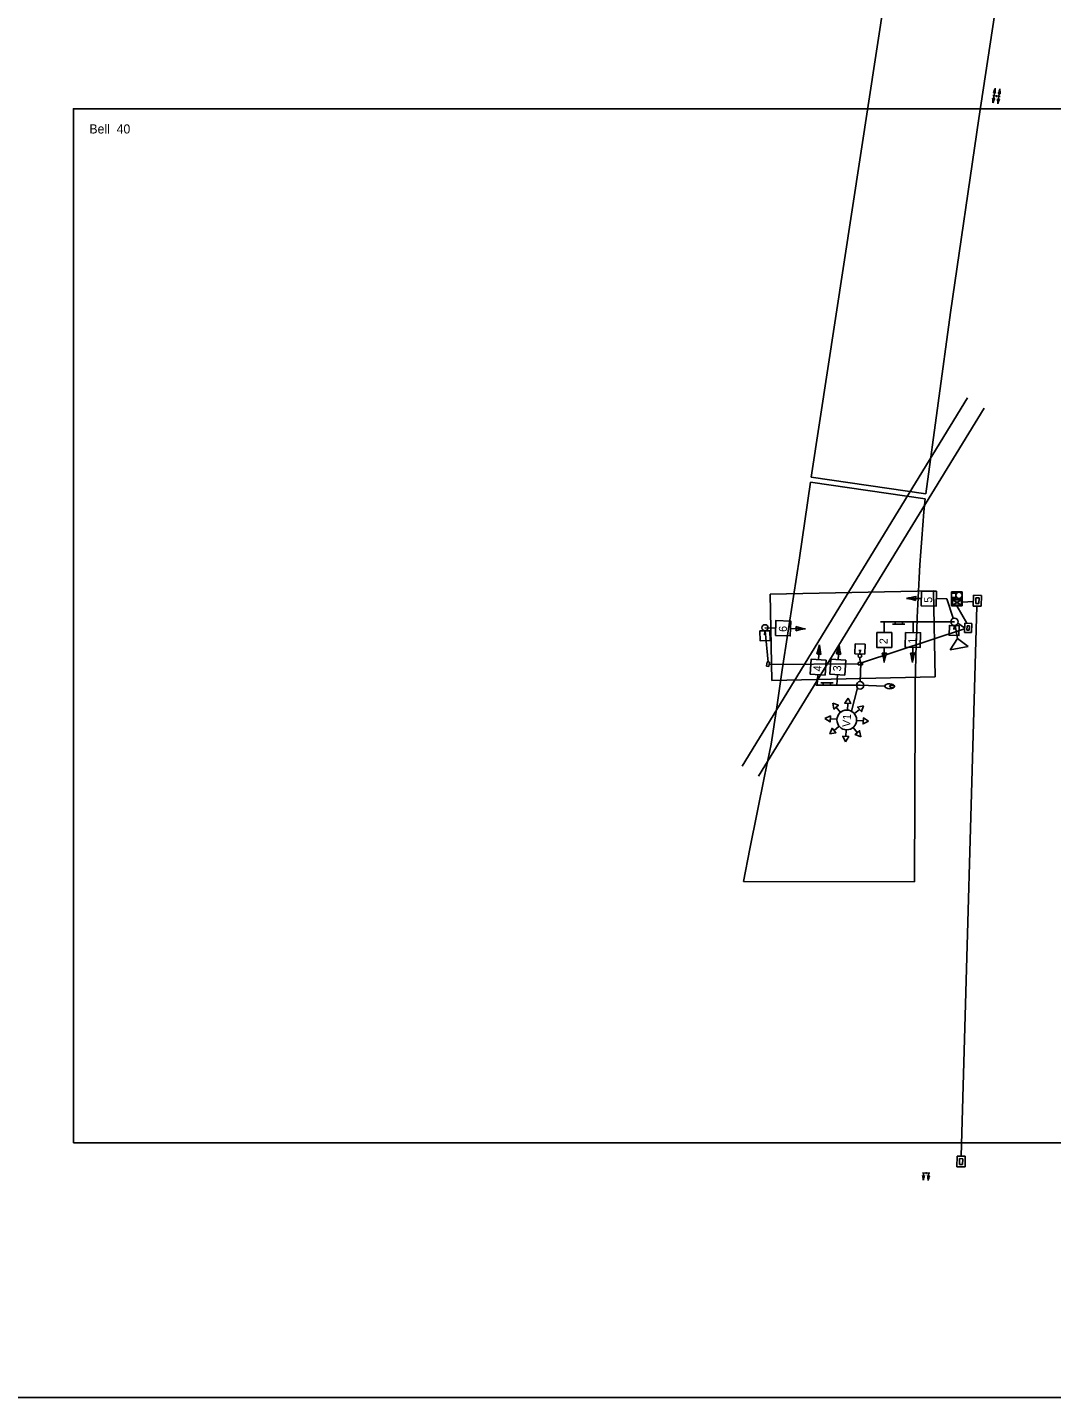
# Model space of a CAD drawing. Extents: x 991933 to 997296, y 1973751 to 1976728.
# Drawn here: x 992632 to 993048, y 1974815 to 1975371 of the extents above; entities that cross this region are included whole.
import ezdxf

# ---------------------------------------------------------------- set-up
doc = ezdxf.new("R2010")
doc.units = 0
for name, color, linetype in [('Level 23', 7, 'Continuous'), ('Level 5', 7, 'Continuous'), ('Level 51', 7, 'Continuous'), ('Level 53', 7, 'Continuous'), ('S_CROSS_DRAIN', 7, 'Continuous'), ('S_CURB', 7, 'Continuous'), ('S_DRIVEWAY', 7, 'Continuous'), ('S_DROP_INLET', 7, 'Continuous'), ('S_PARKING', 7, 'Continuous'), ('S_PAVEMENT_CROWN', 7, 'Continuous'), ('S_SHOULDER', 7, 'Continuous'), ('S_SIDEWALK', 7, 'Continuous')]:
    doc.layers.add(name, color=color, linetype=linetype)

msp = doc.modelspace()

# ---------------------------------------------------------------- linework, layer by layer
at = {"layer": 'Level 23'}
for points in [[(992469.7, 1974814.53), (993459.71, 1974814.53), (993459.71, 1975444.53), (992469.7, 1975444.53)], [(992651, 1974917.97), (993311, 1974917.97), (993311, 1975337.97), (992651, 1975337.97)]]:
    msp.add_lwpolyline(points, close=True, dxfattribs=at)
at = {"layer": 'Level 5'}
for p, q in [((992995.39, 1975481.31), (992950.59, 1975188.29)), ((992950.59, 1975188.29), (992997.14, 1975181.55))]:
    msp.add_line(p, q, dxfattribs=at)
msp.add_lwpolyline([(992997.14, 1975181.55), (993007.15, 1975255.28), (993018.62, 1975333.96), (993027.84, 1975394.67), (993039.93, 1975474.46)], dxfattribs=at)
at = {"layer": 'Level 51'}
for p, q in [((992933.93, 1975140.82), (993000.22, 1975142.21)), ((993000.22, 1975142.21), (993000.95, 1975107.22)), ((992934.66, 1975105.83), (992933.93, 1975140.82)), ((993000.95, 1975107.22), (992934.66, 1975105.83))]:
    msp.add_line(p, q, dxfattribs=at)
at = {"layer": 'Level 53'}
for p, q in [((992996.85, 1975179.57), (992950.31, 1975186.31)), ((992992.51, 1975023.97), (992992.77, 1975093.76)), ((992923.1, 1975024.2), (992992.51, 1975023.97))]:
    msp.add_line(p, q, dxfattribs=at)
msp.add_lwpolyline([(992950.31, 1975186.31), (992950.31, 1975186.31), (992950.31, 1975186.31), (992950.31, 1975186.31), (992950.31, 1975186.31), (992948.02, 1975170.5), (992945.89, 1975155.59), (992943.45, 1975139.92), (992941.13, 1975124.98), (992938.81, 1975110.04), (992936.59, 1975094.9), (992934.31, 1975079.89), (992931.67, 1975066.87), (992928.68, 1975052.14), (992925.71, 1975037.42), (992923.1, 1975024.2)], dxfattribs=at)
msp.add_arc((993972.15, 1975090.11), 979.39, 174.75942, 179.78648, dxfattribs=at)
at = {"layer": 'S_CROSS_DRAIN'}
for p, q in [((992988.64, 1975128.6), (992983.64, 1975128.6)), ((992984.64, 1975129.6), (992984.64, 1975128.6)), ((992987.64, 1975128.6), (992987.64, 1975129.6)), ((992988.64, 1975128.6), (992987.64, 1975128.6)), ((992954.45, 1975104.82), (992955.45, 1975104.82)), ((992954.45, 1975104.82), (992959.45, 1975104.82)), ((992955.45, 1975104.82), (992955.45, 1975103.82)), ((992958.45, 1975103.82), (992958.45, 1975104.82))]:
    msp.add_line(p, q, dxfattribs=at)
at = {"layer": 'S_CURB'}
for p, q in [((993027.31, 1975342.96), (993024.34, 1975343.38)), ((993024.83, 1975343.31), (993024.41, 1975340.32)), ((993024.83, 1975343.31), (993025.26, 1975346.3)), ((993025.66, 1975342.94), (993025.7, 1975343.19)), ((993025.66, 1975342.94), (993025.91, 1975342.91)), ((993025.95, 1975343.16), (993025.7, 1975343.19)), ((993025.95, 1975343.16), (993025.91, 1975342.91)), ((993026.81, 1975343.03), (993026.39, 1975340.04)), ((993026.81, 1975343.03), (993027.24, 1975346.02)), ((992978.75, 1975129.6), (993008.75, 1975129.6)), ((992952.45, 1975103.82), (992970.45, 1975103.82)), ((992998.74, 1974905.72), (992995.74, 1974905.82)), ((992996.24, 1974905.8), (992996.14, 1974902.78)), ((992997.36, 1974905.76), (992997.11, 1974905.77)), ((992997.11, 1974905.52), (992997.11, 1974905.77)), ((992997.11, 1974905.52), (992997.36, 1974905.51)), ((992997.36, 1974905.76), (992997.36, 1974905.51)), ((992998.24, 1974905.73), (992998.14, 1974902.71))]:
    msp.add_line(p, q, dxfattribs=at)
for centre, radius in [((993008.75, 1975129.6), 1.5), ((992931.78, 1975127.17), 1.25), ((992970.35, 1975115.83), 0.75), ((992970.45, 1975103.82), 1.5)]:
    msp.add_circle(centre, radius, dxfattribs=at)
for centre, radius, start, end in [((993024.78, 1975342.93), 0.814, 230.0539, 293.7486), ((993009.67, 1975340.19), 14.74, 0.5096, 8.2477), ((993038.52, 1975336.09), 14.74, 155.5548, 163.2929), ((993011.14, 1975350.54), 14.74, 335.5548, 343.2929), ((993024.89, 1975343.7), 0.814, 50.0539, 113.7486), ((993039.99, 1975346.44), 14.74, 180.5096, 188.2477), ((993026.76, 1975342.65), 0.814, 230.0539, 293.7486), ((993011.65, 1975339.91), 14.74, 0.5096, 8.2477), ((993040.5, 1975335.81), 14.74, 155.5548, 163.2929), ((993013.12, 1975350.26), 14.74, 335.5548, 343.2929), ((993026.87, 1975343.42), 0.814, 50.0539, 113.7486), ((993041.97, 1975346.15), 14.74, 180.5096, 188.2477), ((992996.23, 1974905.41), 0.814, 236.261, 299.9556), ((992981.51, 1974901.06), 14.74, 6.7166, 14.4547), ((993010.63, 1974900.09), 14.74, 161.7618, 169.5), ((992998.23, 1974905.35), 0.814, 236.261, 299.9556), ((992983.5, 1974900.99), 14.74, 6.7166, 14.4547), ((993012.63, 1974900.03), 14.74, 161.7618, 169.5)]:
    msp.add_arc(centre, radius, start, end, dxfattribs=at)
at = {"layer": 'S_DRIVEWAY'}
for p, q in [((993016.49, 1975140.37), (993016.4, 1975136.03)), ((993016.4, 1975136.03), (993019.67, 1975135.96)), ((993019.76, 1975140.29), (993016.49, 1975140.37)), ((993017.47, 1975139.34), (993017.42, 1975137.01)), ((993017.42, 1975137.01), (993018.69, 1975136.98)), ((993018.74, 1975139.31), (993017.47, 1975139.34)), ((993018.69, 1975136.98), (993018.74, 1975139.31)), ((993019.67, 1975135.96), (993019.76, 1975140.29)), ((992931.8, 1975125.92), (992931.83, 1975124.6)), ((993008.23, 1975126.8), (993009.1, 1975126.77)), ((993008.71, 1975128.1), (993008.67, 1975126.78)), ((993012.91, 1975129.05), (993012.82, 1975125.3)), ((993012.82, 1975125.3), (993015.74, 1975125.23)), ((993015.83, 1975128.98), (993012.91, 1975129.05)), ((993013.85, 1975126.28), (993013.89, 1975128.03)), ((993013.89, 1975128.03), (993013.85, 1975126.28)), ((993014.77, 1975126.26), (993013.85, 1975126.28)), ((993013.85, 1975126.28), (993014.77, 1975126.26)), ((993014.81, 1975128.01), (993013.89, 1975128.03)), ((993014.81, 1975128.01), (993013.89, 1975128.03)), ((993014.77, 1975126.26), (993014.81, 1975128.01)), ((993014.77, 1975126.26), (993014.81, 1975128.01)), ((993015.74, 1975125.23), (993015.83, 1975128.98)), ((992931.39, 1975124.59), (992932.26, 1975124.61)), ((992970.85, 1975117.89), (992969.98, 1975117.91)), ((992970.37, 1975116.58), (992970.41, 1975117.9)), ((992932.7, 1975113.31), (992932.48, 1975111.57)), ((992932.48, 1975111.57), (992933.39, 1975111.46)), ((992933.61, 1975113.19), (992932.7, 1975113.31)), ((992933.39, 1975111.46), (992933.61, 1975113.19)), ((992969.66, 1975113.04), (992969.66, 1975112.12)), ((992971.41, 1975113.04), (992969.66, 1975113.04)), ((992969.66, 1975112.12), (992971.41, 1975112.12)), ((992971.41, 1975112.12), (992971.41, 1975113.04)), ((993009.87, 1974912.62), (993009.78, 1974908.28)), ((993009.78, 1974908.28), (993013.05, 1974908.21)), ((993013.14, 1974912.54), (993009.87, 1974912.62)), ((993010.85, 1974911.59), (993010.8, 1974909.26)), ((993010.8, 1974909.26), (993012.07, 1974909.23)), ((993012.12, 1974911.56), (993010.85, 1974911.59)), ((993012.07, 1974909.23), (993012.12, 1974911.56)), ((993013.05, 1974908.21), (993013.14, 1974912.54))]:
    msp.add_line(p, q, dxfattribs=at)
at = {"layer": 'S_DROP_INLET'}
for p, q in [((992922.57, 1975070.96), (993014.09, 1975220.52)), ((992929.25, 1975066.87), (993020.77, 1975216.43))]:
    msp.add_line(p, q, dxfattribs=at)
for points in [[(992933.8, 1975125.96), (992933.88, 1975121.96), (992929.88, 1975121.88), (992929.8, 1975125.88)], [(993010.71, 1975128.04), (993010.58, 1975124.04), (993006.59, 1975124.16), (993006.71, 1975128.16)], [(992968.37, 1975116.64), (992968.5, 1975120.64), (992972.5, 1975120.52), (992972.37, 1975116.52)]]:
    msp.add_lwpolyline(points, close=True, dxfattribs=at)
at = {"layer": 'S_PARKING'}
for p, q in [((993007.6, 1975141.22), (993007.6, 1975139.51)), ((993007.6, 1975141.22), (993009.31, 1975141.22)), ((993007.6, 1975139.51), (993009.31, 1975139.51)), ((993007.6, 1975138.66), (993008.46, 1975138.66)), ((993008.46, 1975139.51), (993008.46, 1975138.66)), ((993009.31, 1975141.22), (993009.31, 1975139.51)), ((993013.77, 1975129.03), (993009.79, 1975136.06)), ((993017.86, 1975136), (993011.51, 1974912.58)), ((993016.44, 1975137.91), (993011.92, 1975137.65)), ((992931.9, 1975125.92), (992933.15, 1975113.25)), ((992971.41, 1975113.04), (993012.86, 1975126.82)), ((993012.87, 1975127.19), (993010.17, 1975129.1)), ((992970.4, 1975115.08), (992970.53, 1975113.04)), ((992933.5, 1975112.32), (992969.66, 1975112.58)), ((992970.5, 1975105.31), (992970.76, 1975112.77))]:
    msp.add_line(p, q, dxfattribs=at)
msp.add_circle((993010.59, 1975140.36), 1.28, dxfattribs=at)
at = {"layer": 'S_PAVEMENT_CROWN'}
for p, q in [((993007.59, 1975141.8), (993007.59, 1975136.06)), ((993011.92, 1975141.8), (993007.59, 1975141.8)), ((993011.92, 1975141.8), (993011.92, 1975136.06)), ((993011.92, 1975138.8), (993007.59, 1975138.8)), ((993011.92, 1975136.06), (993007.59, 1975136.06)), ((993011.59, 1975138.47), (993007.92, 1975138.47)), ((993011.57, 1975136.39), (993007.92, 1975138.47)), ((993007.92, 1975136.39), (993011.59, 1975138.47)), ((993007.92, 1975138.47), (993007.92, 1975136.39)), ((993011.59, 1975136.39), (993007.92, 1975136.39)), ((993011.59, 1975138.47), (993011.59, 1975136.39))]:
    msp.add_line(p, q, dxfattribs=at)
at = {"layer": 'S_SHOULDER'}
for p, q in [((993009.02, 1975128.12), (993009.97, 1975122.85)), ((993006.99, 1975118.25), (993009.97, 1975122.85)), ((993014.37, 1975119.58), (993006.99, 1975118.25)), ((993009.97, 1975122.85), (993014.37, 1975119.58))]:
    msp.add_line(p, q, dxfattribs=at)
at = {"layer": 'S_SIDEWALK'}
for p, q in [((992995.31, 1975139.07), (992989.27, 1975139.14)), ((993005.72, 1975138.97), (993001.38, 1975139.02)), ((993005.72, 1975138.97), (993008.29, 1975131.03)), ((992931.78, 1975127.17), (992936.12, 1975127.05)), ((992942.18, 1975126.9), (992948.22, 1975126.74)), ((992980.22, 1975129.6), (992980.22, 1975125.25)), ((992992.05, 1975129.6), (992991.94, 1975125.25)), ((992953.58, 1975114.21), (992953.95, 1975120.24)), ((992961.58, 1975114.21), (992961.95, 1975120.24)), ((992980.25, 1975119.19), (992980.25, 1975113.15)), ((992991.81, 1975119.19), (992991.66, 1975113.15)), ((992952.95, 1975103.82), (992953.22, 1975108.15)), ((992960.95, 1975103.82), (992961.22, 1975108.15)), ((992969.39, 1975102.75), (992966.91, 1975093.29)), ((992970.45, 1975103.82), (992980.45, 1975103.51)), ((992962.47, 1975092.84), (992960.73, 1975094.93)), ((992965.28, 1975093.75), (992965.45, 1975096.47)), ((992968.11, 1975092.32), (992970.2, 1975094.06)), ((992961.04, 1975090.01), (992958.32, 1975090.18)), ((992961.95, 1975087.21), (992959.86, 1975085.47)), ((992967.59, 1975086.69), (992969.32, 1975084.59)), ((992969.02, 1975089.51), (992971.74, 1975089.34)), ((992964.78, 1975085.77), (992964.61, 1975083.06))]:
    msp.add_line(p, q, dxfattribs=at)
for points in [[(993001.41, 1975142.04), (993001.34, 1975135.97), (992995.28, 1975136.05), (992995.35, 1975142.11)], [(992936.04, 1975124.03), (992936.21, 1975130.09), (992942.27, 1975129.93), (992942.1, 1975123.86)], [(992977.21, 1975125.25), (992983.27, 1975125.25), (992983.27, 1975119.19), (992977.21, 1975119.19)], [(992988.92, 1975125.33), (992994.98, 1975125.18), (992994.83, 1975119.12), (992988.77, 1975119.27)], [(992956.23, 1975107.97), (992950.18, 1975108.34), (992950.56, 1975114.4), (992956.61, 1975114.02)], [(992964.23, 1975107.97), (992958.18, 1975108.34), (992958.56, 1975114.4), (992964.61, 1975114.02)], [(992965.58, 1975098.65), (992964.23, 1975096.54), (992966.66, 1975096.39)], [(992956.14, 1975090.32), (992958.25, 1975088.96), (992958.4, 1975091.4)], [(992959.34, 1975096.61), (992959.8, 1975094.15), (992961.67, 1975095.71)], [(992971.88, 1975095.45), (992969.42, 1975094.99), (992970.98, 1975093.12)], [(992958.18, 1975084.07), (992960.64, 1975084.53), (992959.08, 1975086.4)], [(992973.92, 1975089.21), (992971.81, 1975090.56), (992971.66, 1975088.13)], [(992964.48, 1975080.88), (992965.83, 1975082.98), (992963.39, 1975083.13)], [(992970.72, 1975082.92), (992970.26, 1975085.37), (992968.39, 1975083.82)]]:
    msp.add_lwpolyline(points, close=True, dxfattribs=at)
msp.add_circle((992965.03, 1975089.76), 4, dxfattribs=at)
for centre, radius, start, end in [((992985.22, 1975168.33), 29.47, 277.9152, 285.6533), ((992984.51, 1975110.06), 29.47, 72.9605, 80.6986), ((992994.54, 1975139.08), 1.63, 147.4596, 211.1542), ((992942.96, 1975126.88), 1.63, 326.5672, 30.2619), ((992951.83, 1975097.48), 29.47, 97.0229, 104.761), ((992953.44, 1975155.74), 29.47, 252.0681, 259.8062), ((992925.14, 1975126.45), 29.47, 340.0833, 347.8214), ((992983.31, 1975122.82), 29.47, 185.038, 192.7761), ((992933.14, 1975126.45), 29.47, 340.0833, 347.8214), ((992991.31, 1975122.82), 29.47, 185.038, 192.7761), ((992953.63, 1975114.98), 1.63, 54.5824, 118.277), ((992961.63, 1975114.98), 1.63, 54.5824, 118.277), ((992980.25, 1975118.42), 1.63, 238.1527, 301.8473), ((992951.11, 1975108.74), 29.47, 8.6083, 16.3464), ((993009.39, 1975108.74), 29.47, 163.6536, 171.3917), ((992991.79, 1975118.42), 1.63, 236.7196, 300.4143), ((992962.42, 1975109.47), 29.47, 7.1752, 14.9134), ((993020.68, 1975108.02), 29.47, 162.2205, 169.9586)]:
    msp.add_arc(centre, radius, start, end, dxfattribs=at)
for centre, major_axis in [((992982.45, 1975103.45), (2, -0.06)), ((992983.45, 1975103.42), (-1, 0.03))]:
    msp.add_ellipse(centre, major_axis=major_axis, ratio=0.5, dxfattribs=at)

# ---------------------------------------------------------------- texts
at = {"layer": 'Level 23'}
msp.add_text('Bell  40', height=3.72, rotation=359.9748, dxfattribs=at).set_placement((992657.52, 1975327.93))
at = {"layer": 'S_SIDEWALK'}
for s, rotation, p in [('5', 89.3069, (992999.71, 1975137.31)), ('6', 88.4145, (992940.69, 1975125.48)), ('2', 87.9524, (992981.56, 1975120.47)), ('1', 88.411, (992993.22, 1975120.72)), ('4', 87.9524, (992954.71, 1975109.41)), ('3', 87.9524, (992962.71, 1975109.43)), ('V1', 86.4297, (992966.44, 1975086.79))]:
    msp.add_text(s, height=3.25, rotation=rotation, dxfattribs=at).set_placement(p)

doc.saveas('drawing.dxf')
